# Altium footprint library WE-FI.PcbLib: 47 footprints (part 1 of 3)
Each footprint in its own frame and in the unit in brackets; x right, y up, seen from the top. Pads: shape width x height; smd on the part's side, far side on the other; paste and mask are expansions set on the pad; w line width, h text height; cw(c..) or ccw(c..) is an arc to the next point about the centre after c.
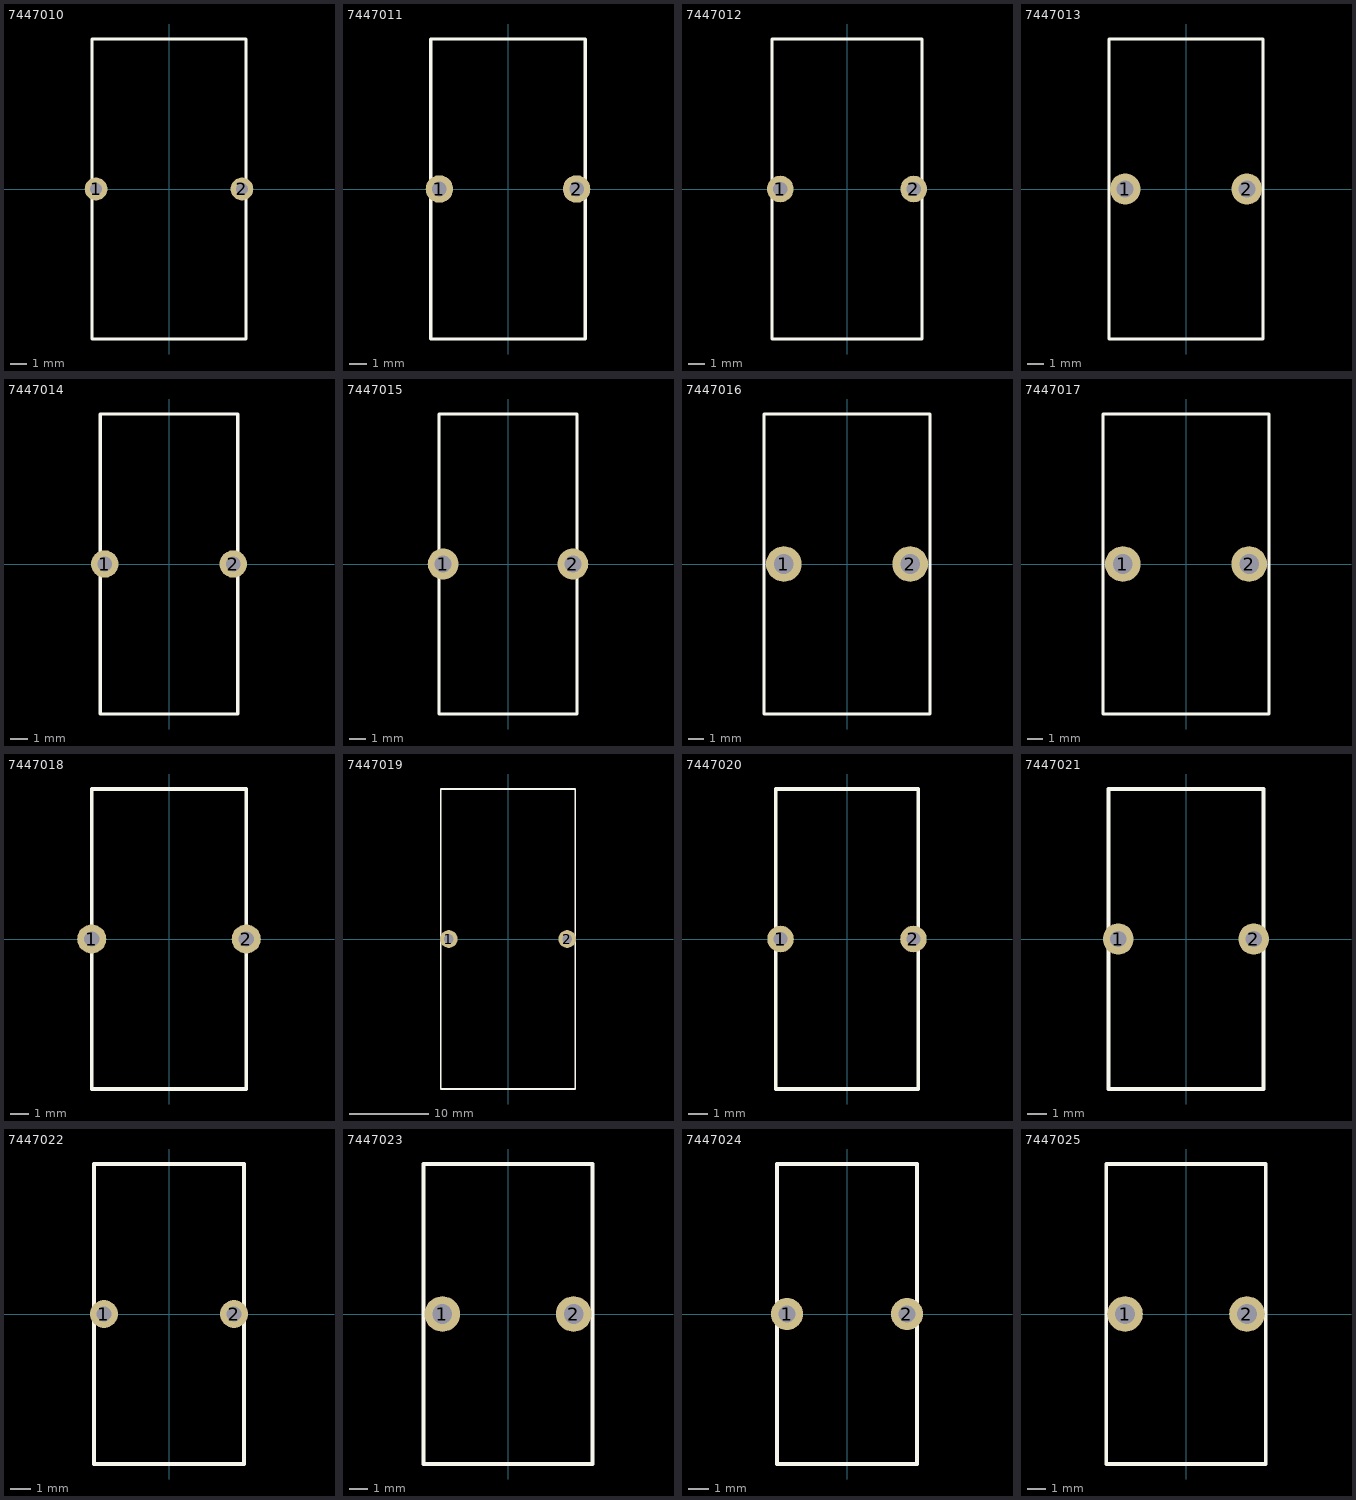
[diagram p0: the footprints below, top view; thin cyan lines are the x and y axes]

## 7447010 [mm] "Body 18.5x9.5mm, 2 leads"
height 18.5
pads (2):
  round 1.4 hole 0.75: 1(-4.5,0) 2(4.5,0)
Top Overlay:
  lines w0.2: -4.75,-9.25 -4.75,9.25 4.75,9.25 4.75,-9.25 -4.75,-9.25
3D body: height 19.9, standoff -14.25, extent -5.42,-9.915 5.42,9.916

## 7447011 [mm] "Body 17.5x9mm, 2 leads"
height 17.5
pads (2):
  round 1.6 hole 0.85: 1(-4,0) 2(4,0)
Top Overlay:
  lines w0.2: -4.5,-8.75 4.5,-8.75 4.5,8.75 -4.5,8.75 -4.5,-8.75
3D body: height 19.35, standoff -13.75, extent -5.12,-9.365 5.12,9.365

## 7447012 [mm] "Body 18x9mm, 2 leads"
height 18
pads (2):
  round 1.6 hole 0.85: 1(-4,0) 2(4,0)
Top Overlay:
  lines w0.2: -4.5,-9 4.5,-9 4.5,9 -4.5,9 -4.5,-9
3D body: height 19.6, standoff -14, extent -5.12,-9.614 5.12,9.614

## 7447013 [mm] "Body 18.5x9.5mm, 2 leads"
height 18.5
pads (2):
  round 1.9 hole 1.05: 1(-3.75,0) 2(3.75,0)
Top Overlay:
  lines w0.2: -4.75,-9.25 -4.75,9.25 4.75,9.25 4.75,-9.25 -4.75,-9.25
3D body: height 20.02, standoff -14.25, extent -5.57,-10.059 5.57,10.058

## 7447014 [mm] "Body 17.5x8mm, 2 leads"
height 17.5
pads (2):
  round 1.6 hole 0.85: 1(-3.75,0) 2(3.75,0)
Top Overlay:
  lines w0.2: -4,-8.75 4,-8.75 4,8.75 -4,8.75 -4,-8.75
3D body: height 19.35, standoff -13.75, extent -4.62,-9.365 4.62,9.365

## 7447015 [mm] "Body 18.5x8.5mm, 2 leads"
height 18.5
pads (2):
  round 1.9 hole 1.05: 1(-4,0) 2(4,0)
Top Overlay:
  lines w0.2: -4.25,-9.25 -4.25,9.25 4.25,9.25 4.25,-9.25 -4.25,-9.25
3D body: height 20.02, standoff -14.25, extent -5.07,-10.059 5.07,10.058

## 7447016 [mm] "Body 19x10.5mm, 2 leads"
height 19
pads (2):
  round 2.25 hole 1.25: 1(-4,0) 2(4,0)
Top Overlay:
  lines w0.2: -5.25,-9.5 5.25,-9.5 5.25,9.5 -5.25,9.5 -5.25,-9.5
3D body: height 17.32, standoff -14.3, extent -4.27,-8.693 4.27,8.694

## 7447017 [mm] "Body 19x10.5mm, 2 leads"
height 19
pads (2):
  round 2.25 hole 1.25: 1(-4,0) 2(4,0)
Top Overlay:
  lines w0.2: -5.25,-9.5 5.25,-9.5 5.25,9.5 -5.25,9.5 -5.25,-9.5
3D body: height 20.93, standoff -14, extent -6.27,-10.493 6.27,10.497

## 7447018 [mm] "Body 16.5x8.5mm, 2 leads"
height 16.5
pads (2):
  round 1.6 hole 0.85: 1(-4.25,0) 2(4.25,0)
Top Overlay:
  lines w0.2: -4.25,-8.25 -4.25,8.25 4.25,8.25 4.25,-8.25 -4.25,-8.25
3D body: height 17.87, standoff -14.25, extent -4.87,-8.833 4.87,8.834

## 7447019 [mm] "Body 38x17mm, 2 leads"
height 38
pads (2):
  round 2.25 hole 1.25: 1(-7.5,0) 2(7.5,0)
Top Overlay:
  lines w0.2: -8.5,-19 -8.5,19 8.5,19 8.5,-19 -8.5,-19
3D body: height 40.49, standoff -13.5, extent -9.52,-20.01 9.52,20.01

## 7447020 [mm] "Body 15.8x7.5mm, 2 leads"
height 15.8
pads (2):
  round 1.4 hole 0.75: 1(-3.5,0) 2(3.5,0)
Top Overlay:
  lines w0.2: -3.75,-7.9 -3.75,7.9 3.75,7.9 3.75,-7.9 -3.75,-7.9
3D body: height 16.89, standoff -14.4, extent -4.26,-8.405 4.26,8.405

## 7447021 [mm] "Body 15.5x8mm, 2 leads"
height 15.5
pads (2):
  round 1.6 hole 0.85: 1(-3.5,0) 2(3.5,0)
Top Overlay:
  lines w0.2: -4,-7.75 4,-7.75 4,7.75 -4,7.75 -4,-7.75
3D body: height 16.84, standoff -14.25, extent -4.62,-8.363 4.62,8.362

## 7447022 [mm] "Body 15x7.5mm, 2 leads"
height 15
pads (2):
  round 1.4 hole 0.75: 1(-3.25,0) 2(3.25,0)
Top Overlay:
  lines w0.2: -3.75,-7.5 3.75,-7.5 3.75,7.5 -3.75,7.5 -3.75,-7.5
3D body: height 16.55, standoff -14, extent -4.32,-8.065 4.32,8.066

## 7447023 [mm] "Body 16x9mm, 2 leads"
height 16
pads (2):
  round 1.9 hole 1.05: 1(-3.5,0) 2(3.5,0)
Top Overlay:
  lines w0.2: -4.5,-8 -4.5,8 4.5,8 4.5,-8 -4.5,-8
3D body: height 17.28, standoff -14.5, extent -5.32,-8.81 5.32,8.807

## 7447024 [mm] "Body 15x7mm, 2 leads"
height 15
pads (2):
  round 1.6 hole 0.85: 1(-3,0) 2(3,0)
Top Overlay:
  lines w0.2: -3.5,-7.5 -3.5,7.5 3.5,7.5 3.5,-7.5 -3.5,-7.5
3D body: height 16.59, standoff -14, extent -4.12,-8.113 4.12,8.113

## 7447025 [mm] "Body 16x8.5mm, 2 leads"
height 16
pads (2):
  round 1.9 hole 1.05: 1(-3.25,0) 2(3.25,0)
Top Overlay:
  lines w0.2: -4.25,-8 -4.25,8 4.25,8 4.25,-8 -4.25,-8
3D body: height 18.28, standoff -13.5, extent -5.07,-8.81 5.07,8.807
